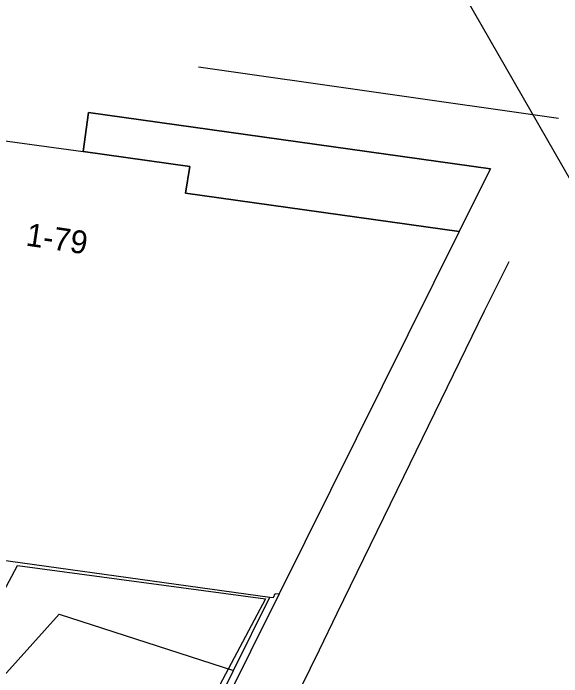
# Model space of a CAD drawing. Extents: x 155640 to 156810, y 382822 to 384046.
# Drawn here: x 156522.05 to 156545.97, y 383629.43 to 383658.37 of the extents above; entities that cross this region are included whole.
import ezdxf

# ---------------------------------------------------------------- set-up
doc = ezdxf.new("R2010")
doc.units = 0
for name, color, linetype in [('IMGEO_Groenvoorziening', 7, 'Continuous'), ('IMGEO_Lijnafwatering', 7, 'Continuous'), ('IMGEO_Muur', 7, 'Continuous'), ('IMGEO_Pand', 7, 'Continuous'), ('IMGEO_Pand_nummerreeks', 7, 'Continuous'), ('IMGEO_Pand_overbouw', 7, 'Continuous'), ('IMGEO_Pand_vergunning_verleend', 7, 'Continuous'), ('IMGEO_Voetgangersgebied_open', 7, 'Continuous'), ('IMGEO_Voetpad_open', 7, 'Continuous')]:
    doc.layers.add(name, color=color, linetype=linetype)

msp = doc.modelspace()

# ---------------------------------------------------------------- linework, layer by layer
at = {"layer": 'IMGEO_Groenvoorziening'}
msp.add_lwpolyline([(156522.46, 383620.094), (156519.317, 383626.898), (156524.054, 383632.157), (156531.663, 383629.7)], dxfattribs=at)
at = {"layer": 'IMGEO_Lijnafwatering'}
for points in [[(156545.834, 383653.783), (156530.135, 383656.021)], [(156535.401, 383630.611), (156536.183, 383632.207), (156539.082, 383638.169), (156542.6, 383645.389), (156543.681, 383647.544)], [(156527.152, 383613.781), (156535.401, 383630.611)]]:
    msp.add_lwpolyline(points, dxfattribs=at)
at = {"layer": 'IMGEO_Muur'}
for points in [[(156533.646, 383633.045), (156507.234, 383579.938), (156469.136, 383609.655), (156454.553, 383640.906)], [(156531.663, 383629.7), (156533.247, 383632.905)], [(156527.439, 383621.156), (156531.663, 383629.7)]]:
    msp.add_lwpolyline(points, dxfattribs=at)
at = {"layer": 'IMGEO_Pand'}
for points in [[(156520.187, 383653.02), (156525.098, 383652.346)], [(156541.504, 383648.852), (156529.566, 383650.531), (156529.757, 383651.696), (156525.098, 383652.346)], [(156541.504, 383648.852), (156533.646, 383633.045)], [(156515.02, 383635.654), (156517.342, 383635.331), (156517.312, 383635.113), (156533.247, 383632.905)], [(156533.247, 383632.905), (156533.395, 383632.884), (156533.479, 383633.068), (156533.646, 383633.045)]]:
    msp.add_lwpolyline(points, dxfattribs=at)
at = {"layer": 'IMGEO_Pand_overbouw'}
msp.add_lwpolyline([(156525.098, 383652.346), (156529.757, 383651.696), (156529.566, 383650.531), (156541.504, 383648.852), (156542.861, 383651.582), (156525.335, 383654.043)], close=True, dxfattribs=at)
at = {"layer": 'IMGEO_Pand_vergunning_verleend'}
msp.add_lwpolyline([(156496.866, 383586.607), (156522.239, 383634.29), (156533.045, 383632.833), (156494.418, 383560.103)], dxfattribs=at)
at = {"layer": 'IMGEO_Voetgangersgebied_open'}
msp.add_lwpolyline([(156541.778, 383659.079), (156554.507, 383636.897)], dxfattribs=at)
at = {"layer": 'IMGEO_Voetpad_open'}
msp.add_lwpolyline([(156525.098, 383652.346), (156525.335, 383654.043), (156542.861, 383651.582), (156541.504, 383648.852)], dxfattribs=at)

# ---------------------------------------------------------------- texts
at = {"layer": 'IMGEO_Pand_nummerreeks'}
msp.add_text('1-79', height=1, rotation=351.5442, dxfattribs=at).set_placement((156522.564, 383648.246))

doc.saveas('drawing.dxf')
